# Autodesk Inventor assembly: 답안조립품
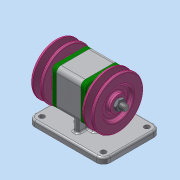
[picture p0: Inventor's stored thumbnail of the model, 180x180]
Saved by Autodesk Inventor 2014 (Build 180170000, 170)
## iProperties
Created: 2020-11
Part Number: 답안조립품
Document SubType Name: Assembly
Designer: kh
Author: kh
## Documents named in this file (11)
- C:\Users\kh\Desktop\701106V1057\답안조립품.iam
- C:\Users\kh\Desktop\701106V1057\본체.ipt
- C:\Users\kh\Desktop\701106V1057\베어링 6004.ipt
- C:\Users\kh\Desktop\701106V1057\축.ipt
- C:\Users\kh\Desktop\701106V1057\커버.ipt
- C:\Users\kh\Desktop\701106V1057\오일 실 17 30 5.ipt
- C:\Users\kh\Desktop\701106V1057\커버_MIR.ipt
- C:\Users\kh\Desktop\701106V1057\키 5 x 5 x 12.ipt
- C:\Users\kh\Desktop\701106V1057\볼트 M4.ipt
- C:\Users\kh\Desktop\701106V1057\V-벨트풀리.ipt
- C:\Users\kh\Desktop\701106V1057\너트 M10x1.ipt
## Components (2 placed, 1 different names)
1. V-벨트풀리:1
2. V-벨트풀리:2
